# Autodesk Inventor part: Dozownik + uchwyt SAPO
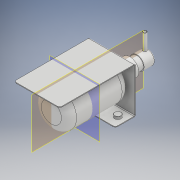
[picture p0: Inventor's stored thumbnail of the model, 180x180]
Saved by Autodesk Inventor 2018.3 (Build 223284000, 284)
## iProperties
Created: 2020-08
Part Number: Dozownik + uchwyt SAPO
Material: Ogólny
Document SubType Name: Modeling
Designer: Verical
Density: 1 g/cm^3
Appearance: Domyślna
Author: Verical
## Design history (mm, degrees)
derived "Dozownik + uchwyt.iam"
node "Bryła1"
node "Butelka.ipt:1"
node "Pompka dozownika.ipt:1"
node "Uchwyt dozownika.ipt:1"
node "Płaszczyzna konstrukcyjna1"
node "Płaszczyzna konstrukcyjna2"
node "Kapselek.ipt:1"
node "Kapselek.ipt:2"
